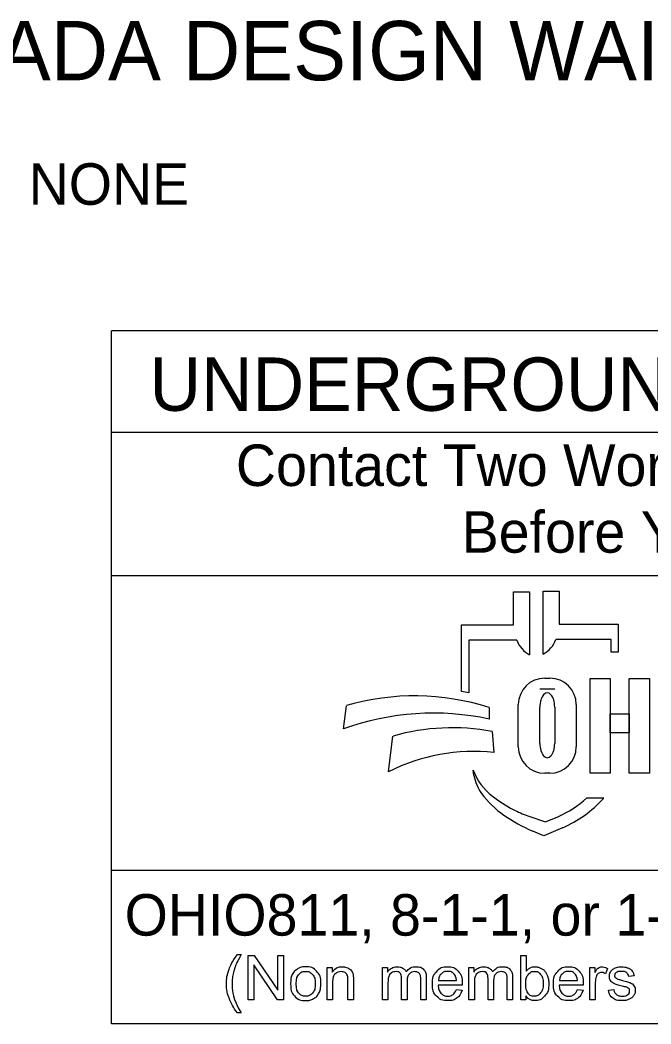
# Model space of a CAD drawing. Extents: x 0 to 36, y 0 to 22.
# Drawn here: x 2.07 to 4.196, y 2.143 to 5.529 of the extents above; entities that cross this region are included whole.
import ezdxf

# ---------------------------------------------------------------- set-up
doc = ezdxf.new("R2010")
doc.units = 0
doc.layers.add('SH_Data', color=7, linetype='Continuous')
doc.layers.add('SH_Text', color=7, linetype='Continuous')

msp = doc.modelspace()

# ---------------------------------------------------------------- linework, layer by layer
at = {"layer": 'SH_Data'}
for p, q in [((2.3775, 2.1428), (2.3775, 4.4803)), ((6.6275, 4.4803), (2.3775, 4.4803)), ((2.3775, 4.1387), (6.6275, 4.1387)), ((2.3775, 3.6553), (6.6275, 3.6553)), ((6.6275, 2.6607), (2.3775, 2.6607)), ((6.6275, 2.1428), (2.3775, 2.1428))]:
    msp.add_line(p, q, dxfattribs=at)
at = {"layer": 'SH_Text'}
for p, q in [((3.7335, 3.4883), (3.7335, 3.5998)), ((3.7335, 3.5998), (3.7872, 3.5998)), ((3.7872, 3.5998), (3.7872, 3.3877)), ((3.8329, 3.39), (3.8329, 3.6021)), ((3.8329, 3.6021), (3.8865, 3.6021)), ((3.8865, 3.6021), (3.8865, 3.4906)), ((3.5576, 3.2644), (3.5576, 3.4883)), ((3.5576, 3.4883), (3.7335, 3.4883)), ((3.8865, 3.4906), (4.0857, 3.4906)), ((4.0857, 3.4906), (4.0857, 3.3968)), ((3.5828, 3.4369), (3.5828, 3.26)), ((3.7439, 3.4369), (3.5828, 3.4369)), ((4.0625, 3.4392), (3.8761, 3.4392)), ((4.0625, 3.3968), (4.0625, 3.4392)), ((4.0857, 3.3968), (4.0625, 3.3968)), ((3.8385, 3.3091), (3.8551, 3.3091)), ((3.8718, 3.2721), (3.822, 3.2721)), ((3.7491, 3.0776), (3.7491, 3.2196)), ((3.9445, 3.2196), (3.9445, 3.0776)), ((3.1602, 3.1381), (3.1696, 3.2162)), ((3.6509, 3.2097), (3.6509, 3.1709)), ((3.822, 3.089), (3.822, 3.2114)), ((3.8718, 3.2114), (3.8718, 3.089)), ((3.6608, 3.1291), (3.6671, 3.0582)), ((3.312, 2.9936), (3.3267, 3.1137)), ((3.5997, 2.9807), (3.5967, 2.9986)), ((3.8551, 2.9882), (3.8385, 2.9882)), ((3.98, 2.9048), (4.0375, 2.9048)), ((3.7816, 2.8444), (3.841, 2.8239)), ((3.841, 2.8239), (3.8821, 2.8417)), ((3.835, 2.7769), (3.7976, 2.7934)), ((3.8983, 2.8044), (3.835, 2.7769))]:
    msp.add_line(p, q, dxfattribs=at)
for points in [[(3.991, 3.3081), (4.0589, 3.3081), (4.0589, 2.9881), (3.991, 2.9881)], [(4.1231, 3.3081), (4.1911, 3.3081), (4.1911, 2.9881), (4.1231, 2.9881)], [(4.0589, 3.1882), (4.1231, 3.1882), (4.1231, 3.1242), (4.0589, 3.1242)]]:
    msp.add_lwpolyline(points, close=True, dxfattribs=at)
for points in [[(2.8021, 2.3766), (2.8153, 2.3766)], [(2.8389, 2.2239), (2.8389, 2.3741), (2.8592, 2.3741), (2.9382, 2.2561), (2.9382, 2.3741), (2.9572, 2.3741), (2.9572, 2.2239), (2.9369, 2.2239), (2.8579, 2.3419), (2.8579, 2.2239), (2.8389, 2.2239)], [(3.7743, 2.2239), (3.7573, 2.2239), (3.7573, 2.3741), (3.7757, 2.3741), (3.7757, 2.3206)], [(3.1048, 2.2239), (3.1048, 2.3328), (3.1214, 2.3328), (3.1214, 2.3173)], [(3.2912, 2.2239), (3.2912, 2.3328), (3.3077, 2.3328), (3.3077, 2.3174)], [(3.5826, 2.2239), (3.5826, 2.3328), (3.5991, 2.3328), (3.5991, 2.3174)], [(3.9904, 2.2239), (3.9904, 2.3328), (4.007, 2.3328), (4.007, 2.3163)], [(4.0495, 2.3293), (4.043, 2.3122)], [(4.1394, 2.3046), (4.1213, 2.3022)], [(3.1233, 2.2833), (3.1233, 2.2239), (3.1048, 2.2239)], [(3.1932, 2.2908), (3.1932, 2.2239), (3.1748, 2.2239), (3.1748, 2.2901)], [(3.3097, 2.2803), (3.3097, 2.2239), (3.2912, 2.2239)], [(3.3743, 2.2871), (3.3743, 2.2239), (3.3559, 2.2239), (3.3559, 2.2946)], [(3.4388, 2.2986), (3.4388, 2.2239), (3.4203, 2.2239), (3.4203, 2.2924)], [(3.56, 2.2736), (3.4788, 2.2736)], [(3.4799, 2.2887), (3.5406, 2.2887)], [(3.601, 2.2803), (3.601, 2.2239), (3.5826, 2.2239)], [(3.6657, 2.2871), (3.6657, 2.2239), (3.6473, 2.2239), (3.6473, 2.2946)], [(3.7301, 2.2986), (3.7301, 2.2239), (3.7117, 2.2239), (3.7117, 2.2924)], [(3.968, 2.2736), (3.8868, 2.2736)], [(3.8879, 2.2887), (3.9486, 2.2887)], [(4.0088, 2.2809), (4.0088, 2.2239), (3.9904, 2.2239)], [(3.5404, 2.2591), (3.5595, 2.2567)], [(3.7743, 2.2375), (3.7743, 2.2239)], [(3.9484, 2.2591), (3.9675, 2.2567)], [(4.053, 2.2564), (4.0712, 2.2593)], [(2.8153, 2.1798), (2.8021, 2.1798)]]:
    msp.add_lwpolyline(points, dxfattribs=at)
for centre, radius, start, end in [((3.8353, 3.4736), 0.0985, 201.9296, 240.7469), ((3.7847, 3.476), 0.0985, 299.2531, 338.0704), ((3.8385, 3.2196), 0.0895, 90, 180), ((3.8551, 3.2196), 0.0895, 0, 90), ((3.4295, 2.4554), 0.8191, 79.2074, 81.0007), ((3.3997, 2.4302), 0.8191, 72.1402, 106.3144), ((3.4628, 2.2991), 0.8919, 77.8238, 109.8274), ((3.5267, 2.4094), 0.7322, 79.44, 105.8467), ((3.5987, 2.4262), 0.6357, 83.8248, 116.8021), ((3.8385, 3.0776), 0.0895, 180, 270), ((3.8551, 3.0776), 0.0895, 270, 0), ((3.7841, 3.0707), 0.2008, 201.0457, 232.5314), ((3.741, 3.0048), 0.1433, 189.6817, 216.0884), ((3.8747, 3.1022), 0.3088, 216.0884, 235.7167), ((3.9766, 3.3219), 0.5173, 232.5314, 241.794), ((3.7387, 3.1722), 0.3602, 293.4582, 312.0712), ((3.7387, 3.1722), 0.401, 293.4582, 317.8286), ((4.0412, 3.3465), 0.6044, 235.7167, 246.2325), ((3.8914, 3.1631), 0.3371, 241.794, 250.9821)]:
    msp.add_arc(centre, radius, start, end, dxfattribs=at)
for centre, start_param, end_param in [((3.8469, 3.2114), 4.712389, 7.853982), ((3.8469, 3.089), 1.570796, 4.712389)]:
    msp.add_ellipse(centre, major_axis=(0, 0.0484), ratio=0.514403, start_param=start_param, end_param=end_param, dxfattribs=at)
for points in [[(2.8021, 2.1798), (2.7869, 2.199), (2.7763, 2.2248), (2.7657, 2.2506), (2.7657, 2.2783), (2.7657, 2.3026), (2.7736, 2.325), (2.7829, 2.3509), (2.8021, 2.3766)], [(2.8153, 2.3766), (2.8029, 2.3553), (2.7989, 2.3462), (2.7927, 2.332), (2.7891, 2.3167), (2.7847, 2.2975), (2.7847, 2.2782), (2.7847, 2.2289), (2.8153, 2.1798)], [(2.9814, 2.2783), (2.9814, 2.3085), (2.9981, 2.3231), (3.0122, 2.3352), (3.0323, 2.3352), (3.0547, 2.3352), (3.069, 2.3205), (3.0832, 2.3058), (3.0832, 2.2799), (3.0832, 2.2589), (3.0769, 2.2469), (3.0706, 2.2348), (3.0586, 2.2282), (3.0466, 2.2215), (3.0323, 2.2215), (3.0095, 2.2215), (2.9954, 2.2362), (2.9814, 2.2508), (2.9814, 2.2783)], [(3.0003, 2.2783), (3.0003, 2.2574), (3.0094, 2.247), (3.0185, 2.2366), (3.0323, 2.2366), (3.046, 2.2366), (3.0551, 2.2471), (3.0642, 2.2575), (3.0642, 2.279), (3.0642, 2.2991), (3.0551, 2.3095), (3.0459, 2.3199), (3.0323, 2.3199), (3.0185, 2.3199), (3.0094, 2.3096), (3.0003, 2.2992), (3.0003, 2.2783)], [(3.1214, 2.3173), (3.1334, 2.3352), (3.156, 2.3352), (3.1659, 2.3352), (3.1741, 2.3316), (3.1823, 2.3281), (3.1864, 2.3224), (3.1905, 2.3166), (3.1922, 2.3087), (3.1932, 2.3036), (3.1932, 2.2908)], [(3.1748, 2.2901), (3.1748, 2.3013), (3.1726, 2.3069), (3.1705, 2.3125), (3.165, 2.3158), (3.1595, 2.3191), (3.1521, 2.3191), (3.1404, 2.3191), (3.1318, 2.3117), (3.1233, 2.3042), (3.1233, 2.2833)], [(3.3077, 2.3174), (3.3128, 2.3254), (3.3214, 2.3303), (3.3299, 2.3352), (3.3407, 2.3352), (3.3528, 2.3352), (3.3606, 2.3301), (3.3683, 2.3251), (3.3715, 2.3161), (3.3844, 2.3352), (3.4051, 2.3352), (3.4213, 2.3352), (3.43, 2.3262), (3.4388, 2.3172), (3.4388, 2.2986)], [(3.3559, 2.2946), (3.3559, 2.3069), (3.3514, 2.313), (3.3469, 2.3191), (3.3366, 2.3191), (3.3288, 2.3191), (3.3222, 2.315), (3.3156, 2.311), (3.3126, 2.3031), (3.3097, 2.2952), (3.3097, 2.2803)], [(3.4203, 2.2924), (3.4203, 2.3035), (3.4185, 2.3083), (3.4168, 2.3132), (3.412, 2.3162), (3.4073, 2.3191), (3.401, 2.3191), (3.3895, 2.3191), (3.3819, 2.3115), (3.3743, 2.3039), (3.3743, 2.2871)], [(3.5595, 2.2567), (3.555, 2.24), (3.5428, 2.2307), (3.5306, 2.2215), (3.5117, 2.2215), (3.4878, 2.2215), (3.4738, 2.2362), (3.4598, 2.2509), (3.4598, 2.2774), (3.4598, 2.3049), (3.474, 2.32), (3.4881, 2.3352), (3.5106, 2.3352), (3.5324, 2.3352), (3.5463, 2.3203), (3.5601, 2.3055), (3.5601, 2.2785), (3.5601, 2.2769), (3.56, 2.2736)], [(3.5406, 2.2887), (3.5394, 2.3025), (3.5337, 2.3094), (3.5249, 2.3201), (3.5108, 2.3201), (3.4981, 2.3201), (3.4894, 2.3115), (3.4808, 2.303), (3.4799, 2.2887)], [(3.5991, 2.3174), (3.6042, 2.3254), (3.6127, 2.3303), (3.6212, 2.3352), (3.6321, 2.3352), (3.6442, 2.3352), (3.6519, 2.3301), (3.6597, 2.3251), (3.6628, 2.3161), (3.6758, 2.3352), (3.6965, 2.3352), (3.7127, 2.3352), (3.7214, 2.3262), (3.7301, 2.3172), (3.7301, 2.2986)], [(3.6473, 2.2946), (3.6473, 2.3069), (3.6428, 2.313), (3.6383, 2.3191), (3.628, 2.3191), (3.6202, 2.3191), (3.6136, 2.315), (3.607, 2.311), (3.604, 2.3031), (3.601, 2.2952), (3.601, 2.2803)], [(3.7117, 2.2924), (3.7117, 2.3035), (3.7099, 2.3083), (3.7081, 2.3132), (3.7034, 2.3162), (3.6987, 2.3191), (3.6923, 2.3191), (3.6809, 2.3191), (3.6733, 2.3115), (3.6657, 2.3039), (3.6657, 2.2871)], [(3.7741, 2.2792), (3.7741, 2.2596), (3.7794, 2.2509), (3.7881, 2.2366), (3.8029, 2.2366), (3.815, 2.2366), (3.8238, 2.2471), (3.8326, 2.2576), (3.8326, 2.2784), (3.8326, 2.2998), (3.8241, 2.3099), (3.8157, 2.3201), (3.8038, 2.3201), (3.7917, 2.3201), (3.7829, 2.3096), (3.7741, 2.299), (3.7741, 2.2792)], [(3.7757, 2.3206), (3.7874, 2.3352), (3.8055, 2.3352), (3.8155, 2.3352), (3.8245, 2.3311), (3.8335, 2.3271), (3.8392, 2.3198), (3.845, 2.3124), (3.8483, 2.3021), (3.8516, 2.2918), (3.8516, 2.28), (3.8516, 2.252), (3.8378, 2.2368), (3.8239, 2.2215), (3.8046, 2.2215), (3.7853, 2.2215), (3.7743, 2.2375)], [(3.9675, 2.2567), (3.963, 2.24), (3.9508, 2.2307), (3.9386, 2.2215), (3.9196, 2.2215), (3.8958, 2.2215), (3.8818, 2.2362), (3.8678, 2.2509), (3.8678, 2.2774), (3.8678, 2.3049), (3.882, 2.32), (3.8961, 2.3352), (3.9186, 2.3352), (3.9404, 2.3352), (3.9543, 2.3203), (3.9681, 2.3055), (3.9681, 2.2785), (3.9681, 2.2769), (3.968, 2.2736)], [(3.9486, 2.2887), (3.9474, 2.3025), (3.9417, 2.3094), (3.9328, 2.3201), (3.9188, 2.3201), (3.9061, 2.3201), (3.8974, 2.3115), (3.8888, 2.303), (3.8879, 2.2887)], [(4.007, 2.3163), (4.0133, 2.3278), (4.0187, 2.3315), (4.0241, 2.3352), (4.0305, 2.3352), (4.0398, 2.3352), (4.0495, 2.3293)], [(4.043, 2.3122), (4.0363, 2.3162), (4.0295, 2.3162), (4.0235, 2.3162), (4.0187, 2.3125), (4.0139, 2.3089), (4.0119, 2.3024), (4.0088, 2.2926), (4.0088, 2.2809)], [(4.1213, 2.3022), (4.1201, 2.3106), (4.1142, 2.3153), (4.1083, 2.3201), (4.0975, 2.3201), (4.0848, 2.3201), (4.0794, 2.3159), (4.0739, 2.3116), (4.0739, 2.306), (4.0739, 2.3024), (4.0762, 2.2995), (4.0785, 2.2966), (4.0833, 2.2946), (4.086, 2.2936), (4.0996, 2.2899), (4.1192, 2.2847), (4.1269, 2.2813), (4.1347, 2.278), (4.1391, 2.2717), (4.1435, 2.2653), (4.1435, 2.2559), (4.1435, 2.2467), (4.1381, 2.2386), (4.1327, 2.2304), (4.1226, 2.226), (4.1124, 2.2215), (4.0996, 2.2215), (4.0784, 2.2215), (4.0672, 2.2303), (4.0561, 2.2391), (4.053, 2.2564)], [(4.0712, 2.2593), (4.0727, 2.2483), (4.0798, 2.2425), (4.0868, 2.2366), (4.0995, 2.2366), (4.1122, 2.2366), (4.1184, 2.2418), (4.1245, 2.247), (4.1245, 2.254), (4.1245, 2.2602), (4.1191, 2.2638), (4.1153, 2.2663), (4.1002, 2.2701), (4.0799, 2.2752), (4.072, 2.2789), (4.0642, 2.2827), (4.0601, 2.2893), (4.0561, 2.2959), (4.0561, 2.3038), (4.0561, 2.3111), (4.0594, 2.3173), (4.0628, 2.3235), (4.0685, 2.3276), (4.0728, 2.3308), (4.0803, 2.333), (4.0877, 2.3352), (4.0962, 2.3352), (4.109, 2.3352), (4.1187, 2.3315), (4.1284, 2.3278), (4.133, 2.3215), (4.1377, 2.3152), (4.1394, 2.3046)], [(3.4788, 2.2736), (3.4799, 2.2557), (3.489, 2.2462), (3.4981, 2.2366), (3.5117, 2.2366), (3.5219, 2.2366), (3.5291, 2.242), (3.5362, 2.2473), (3.5404, 2.2591)], [(3.8868, 2.2736), (3.8879, 2.2557), (3.897, 2.2462), (3.9061, 2.2366), (3.9197, 2.2366), (3.9299, 2.2366), (3.937, 2.242), (3.9442, 2.2473), (3.9484, 2.2591)]]:
    msp.add_open_spline(points, degree=3, dxfattribs=at)

# ---------------------------------------------------------------- texts
for s, height, p in [('ADA DESIGN WAIVERS', 0.2, (1.9944, 5.3256)), ('  NONE', 0.14, (1.9944, 4.9056)), ('UNDERGROUND UTILITIES', 0.18, (2.5057, 4.2106)), ('Contact Two Working Days', 0.14, (2.7972, 3.9571)), ('Before You Dig', 0.14, (3.5583, 3.7321)), ('OHIO811, 8-1-1, or 1-800-362-2764', 0.14, (2.422, 2.4406))]:
    msp.add_text(s, height=height, dxfattribs=at).set_placement(p)

doc.saveas('drawing.dxf')
